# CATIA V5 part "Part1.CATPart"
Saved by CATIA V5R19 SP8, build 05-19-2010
Part number: Simulation Statique
Bounding box of the stored display mesh (mm): x 0 to 0, y -406.144 to 889.064, z -569.974 to 636.447
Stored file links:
  D:\Documents\1_Travail\1 - ac-limoges.fr\OneDrive - ac-limoges.fr\STI2D_Turgot\2 -2I2D\3_SEQUENCE_Serre_Connectée\3- Spécificités\ITEC\EC 3 Ouverture automatique\Simulation  Ouverture Automatique\Part1.CATPart
  D:\Documents\1_Travail\1 - ac-limoges.fr\OneDrive - ac-limoges.fr\STI2D_Turgot\2 -2I2D\3_SEQUENCE_Serre_Connectée\Dossier technique_SERRE\Maquettes_CATIA\Simulation Statique Ouverture Automatique\0-Simu_Statique_Ouverture automatique .CATProduct
  D:\Documents\1_Travail\1 - ac-limoges.fr\OneDrive - ac-limoges.fr\STI2D_Turgot\2 -2I2D\3_SEQUENCE_Serre_Connectée\3- Spécificités\ITEC\EC 3 Ouverture automatique\Simulation  Ouverture Automatique\Axe de bras L.CATPart
  D:\Documents\1_Travail\1 - ac-limoges.fr\OneDrive - ac-limoges.fr\STI2D_Turgot\2 -2I2D\3_SEQUENCE_Serre_Connectée\3- Spécificités\ITEC\EC 3 Ouverture automatique\Simulation  Ouverture Automatique\Bague_epaulee.CATPart
  D:\Documents\1_Travail\1 - ac-limoges.fr\OneDrive - ac-limoges.fr\STI2D_Turgot\2 -2I2D\3_SEQUENCE_Serre_Connectée\3- Spécificités\ITEC\EC 3 Ouverture automatique\Simulation  Ouverture Automatique\T d''assemblage.CATPart
  D:\Documents\1_Travail\1 - ac-limoges.fr\OneDrive - ac-limoges.fr\STI2D_Turgot\2 -2I2D\3_SEQUENCE_Serre_Connectée\3- Spécificités\ITEC\EC 3 Ouverture automatique\Simulation  Ouverture Automatique\Entretoise.CATPart
  D:\Documents\1_Travail\1 - ac-limoges.fr\OneDrive - ac-limoges.fr\STI2D_Turgot\2 -2I2D\3_SEQUENCE_Serre_Connectée\3- Spécificités\ITEC\EC 3 Ouverture automatique\Simulation  Ouverture Automatique\Lucarne.CATPart
  D:\Documents\1_Travail\1 - ac-limoges.fr\OneDrive - ac-limoges.fr\STI2D_Turgot\2 -2I2D\3_SEQUENCE_Serre_Connectée\3- Spécificités\ITEC\EC 3 Ouverture automatique\Simulation  Ouverture Automatique\Attache fenetre.CATPart
  D:\Documents\1_Travail\1 - ac-limoges.fr\OneDrive - ac-limoges.fr\STI2D_Turgot\2 -2I2D\3_SEQUENCE_Serre_Connectée\Dossier technique_SERRE\Maquettes_CATIA\Corr_Simulation statique Ouverture automatique\Vitre.CATPart
  D:\Documents\1_Travail\1 - ac-limoges.fr\OneDrive - ac-limoges.fr\STI2D_Turgot\2 -2I2D\3_SEQUENCE_Serre_Connectée\3- Spécificités\ITEC\EC 3 Ouverture automatique\Simulation  Ouverture Automatique\Bras K.CATPart
  D:\Documents\1_Travail\1 - ac-limoges.fr\OneDrive - ac-limoges.fr\STI2D_Turgot\2 -2I2D\3_SEQUENCE_Serre_Connectée\Dossier technique_SERRE\Maquettes_CATIA\Ouverture_automatique_ACD_Corrigé\Cadre de lucarne.CATPart
  D:\Documents\1_Travail\1 - ac-limoges.fr\OneDrive - ac-limoges.fr\STI2D_Turgot\2 -2I2D\3_SEQUENCE_Serre_Connectée\3- Spécificités\ITEC\EC 3 Ouverture automatique\Simulation  Ouverture Automatique\Bague filetee.CATPart
  D:\Documents\1_Travail\1 - ac-limoges.fr\OneDrive - ac-limoges.fr\STI2D_Turgot\2 -2I2D\3_SEQUENCE_Serre_Connectée\3- Spécificités\ITEC\EC 3 Ouverture automatique\Simulation  Ouverture Automatique\0-Simulation_Ouverture automatique .CATProduct
  D:\Documents\1_Travail\1 - ac-limoges.fr\OneDrive - ac-limoges.fr\STI2D_Turgot\2 -2I2D\3_SEQUENCE_Serre_Connectée\3- Spécificités\ITEC\EC 3 Ouverture automatique\Simulation  Ouverture Automatique\Corps_de_verin.CATPart
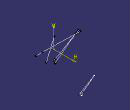
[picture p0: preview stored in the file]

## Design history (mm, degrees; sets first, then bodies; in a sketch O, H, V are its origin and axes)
Parameters
  `Poids lucarne` = 50 mm
External parameters (linked from other documents)
  External.Longueur.1 = 98.658 mm
  External.Longueur = 71.917 mm
AxisSystem1: origin (0, 0, 0), X (1, 0, 0), Y (0, 1, 0), Z (0, 0, 1)
TTRSSet1
f4a2d38f3ddc11d3a929006094b99c4b_11 "CATTPSSet"
Set1
  DatumCurve1 to DatumCurve5: linked copy from another document
Body1 (main body)
  Sketch1 "Solide 3-4-5-6" on YZ plane of AxisSystem1, origin (0, 0, 0), H (0, 1, 0), V (0, 0, 1)
    line L1 (496.9588, 554.2388) -> (-380.832, -302.2469)
    reference projected point E1 (144.5705, 210.4035) from edge of DatumCurve1
    reference projected point E2 (118.9201, 185.3756) from edge of DatumCurve2
    coincidence: L1 E1, L1 E2
  Sketch2 "Solide 2" on YZ plane of AxisSystem1, origin (0, 0, 0), H (0, 1, 0), V (0, 0, 1)
    line L1 (-71.0668, 0) -> (-21.0668, 0)
    point P1 (-71.0668, 0)
    line L2 (-170.9742, -333.9399) -> (3.5856, 249.525)
    line L3 (563.6337, 619.2954) -> (-406.1437, -326.9441)
    reference projected line E1 (496.9588, 554.2388) -> (-380.832, -302.2469) from Sketch1
    reference projected point E2 (-147.5, -255.4775) from edge of DatumCurve3
    length L1 = 50 {= `Poids lucarne`}
    coincidence: P1 H, L2 P1, L3 P1, L3 E1, E2 L2
    horizontal: L1 H
  Sketch3 "Solide 5-6" on YZ plane of AxisSystem1, origin (0, 0, 0), H (0, 1, 0), V (0, 0, 1)
    line L1 (28.1467, -168.1613) -> (538.8146, 636.2815)
    reference projected line E1 through (211.3617, 120.4529) direction (-0.5359, -0.8443) from edge of DatumCurve4
    coincidence: L1 E1
  Sketch4 "Solide 4" on yz-plane, origin (0, 0, 0), H (0, 1, 0), V (0, 0, 1)
    line L1 (-247.6325, -172.2803) -> (581.2117, 636.4468)
    line L2 (0, -212.5001) -> (470.0914, 528.0235)
    point P3 (0, -212.5001)
    point P4 (470.0914, 528.0235)
    line L3 (22.7509, -250.2519) -> (493.9341, 569.5046)
    reference projected line E1 (563.6337, 619.2954) -> (-406.1437, -326.9441) from Sketch2.L3
    reference projected line E2 (104.2071, -48.3452) -> (614.8749, 756.0975) from Sketch3
    reference projected point E3 (132.2084, -59.8196) from edge of DatumCurve5
    coincidence: P3 V, L1 E1, L2 E2, P4 L1, L3 P4, L3 E3
  Sketch5 "Dynamique" on yz-plane, origin (0, 0, 0), H (0, 1, 0), V (0, 0, 1)
    line L1 (561.1008, -569.974) -> (611.1008, -569.974)
    line L2 (611.1008, -569.974) -> (631.7139, -501.0747)
    line L3 (631.7139, -501.0747) -> (561.1008, -569.974)
    reference projected line E1 (-247.6325, -172.2803) -> (581.2117, 636.4468) from Sketch4.L1
    reference projected line E2 (-170.9742, -333.9399) -> (3.5856, 249.525) from Sketch2.L2
    line L4 (561.1008, -569.974) -> (889.0636, -53.342)
    line L5 (889.0636, -53.342) -> (631.7139, -501.0747)
    reference projected line E3 (28.1467, -168.1613) -> (538.8146, 636.2815) from Sketch3
    reference projected line E4 (103.1691, -110.3418) -> (574.3522, 709.4148) from Sketch4.L3
    length L1 = 50 {= `Poids lucarne`}
    horizontal: L1 H
    parallelism: L3 E1, L2 E2, L4 E3, L5 E4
